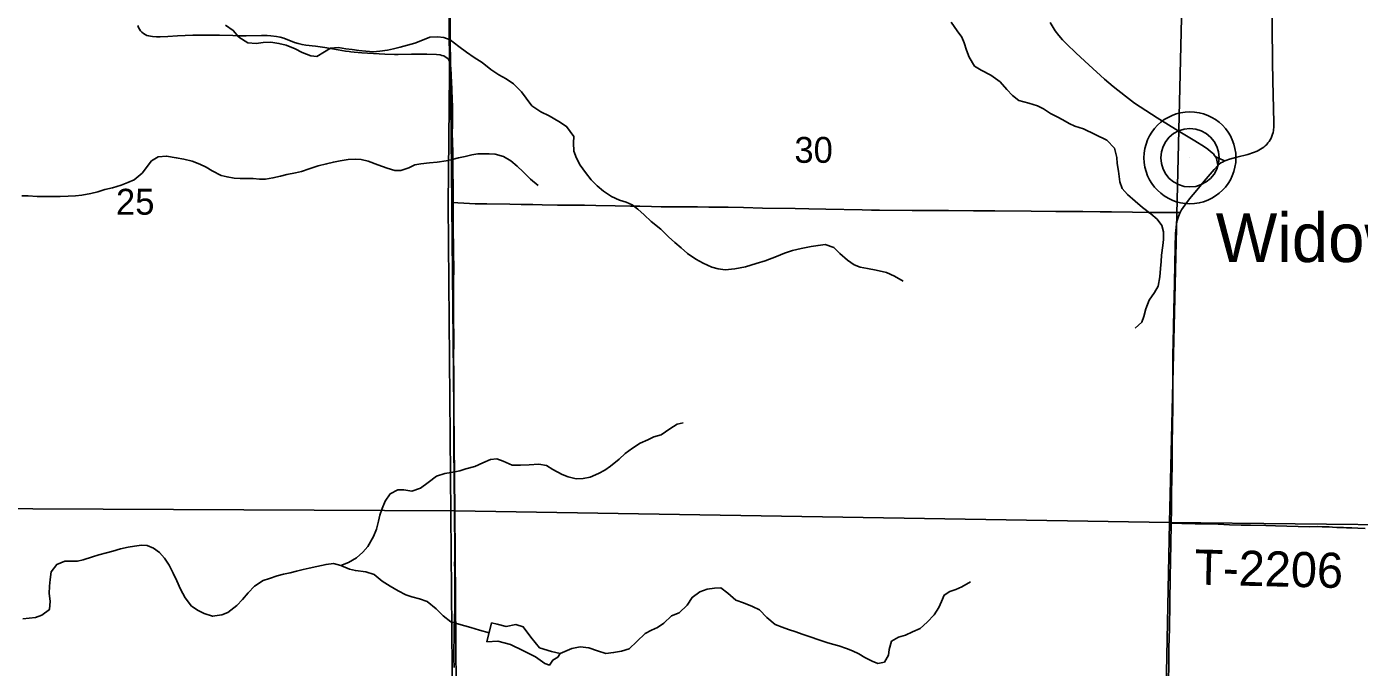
# Model space of a CAD drawing. Extents: x 1874609 to 2204689, y 815661 to 1281160.
# Drawn here: x 2009363 to 2020755, y 997204 to 1002678 of the extents above; entities that cross this region are included whole.
import ezdxf

# ---------------------------------------------------------------- set-up
doc = ezdxf.new("R2010")
doc.units = 0
for name, color, linetype in [('GM_X_County_Road', 7, 'Continuous'), ('GM_X_Minor_Lake', 7, 'Continuous'), ('GM_X_Minor_River', 7, 'Continuous'), ('GM_X_Section', 7, 'Continuous'), ('GM_X_Section_Text', 7, 'Continuous'), ('GM_X_State_Route', 7, 'Continuous'), ('GM_X_Township', 7, 'Continuous'), ('GM_X_Township_Road', 7, 'Continuous'), ('GM_X_Township_Road_Text', 7, 'Continuous'), ('GM_X_Unincorporated', 7, 'Continuous'), ('GM_X_Unincorporated_Location', 7, 'Continuous'), ('GM_X_Unincorporated_Text', 7, 'Continuous')]:
    doc.layers.add(name, color=color, linetype=linetype)

msp = doc.modelspace()

# ---------------------------------------------------------------- linework, layer by layer
at = {"layer": 'GM_X_County_Road'}
for points in [[(2018113, 1002715), (2018137, 1002672), (2018155, 1002644), (2018185, 1002604), (2018217, 1002567), (2018251, 1002531), (2018334, 1002452), (2018443, 1002352), (2018577, 1002230), (2018652, 1002167), (2018755, 1002085), (2018834, 1002026), (2018929, 1001961), (2019026, 1001899), (2019221, 1001779), (2019348, 1001703), (2019432, 1001652), (2019459, 1001633), (2019484, 1001613), (2019508, 1001591), (2019518, 1001579), (2019527, 1001567), (2019528, 1001565)], [(2019528, 1001565), (2019533, 1001552), (2019538, 1001539), (2019541, 1001524), (2019543, 1001510), (2019546, 1001492)], [(2019528, 1001565), (2019550, 1001554), (2019571, 1001545), (2019590, 1001538), (2019606, 1001532)]]:
    msp.add_lwpolyline(points, dxfattribs=at)
at = {"layer": 'GM_X_Minor_Lake'}
for points in [[(2013296, 997421), (2013392, 997429), (2013498, 997399), (2013610, 997346), (2013712, 997294), (2013792, 997238), (2013832, 997224), (2013861, 997266), (2013903, 997290), (2013925, 997322), (2013851, 997340), (2013748, 997372), (2013674, 997461), (2013608, 997549), (2013546, 997569), (2013462, 997553), (2013386, 997573), (2013338, 997583)], [(2013338, 997583), (2013296, 997421)]]:
    msp.add_lwpolyline(points, dxfattribs=at)
at = {"layer": 'GM_X_Minor_River'}
for points in [[(2017266, 1002716), (2017318, 1002642), (2017356, 1002590), (2017378, 1002539), (2017398, 1002479), (2017420, 1002417), (2017466, 1002342), (2017522, 1002306), (2017604, 1002265), (2017684, 1002207), (2017743, 1002142), (2017791, 1002090), (2017845, 1002048), (2017929, 1002025), (2018004, 1002001), (2018054, 1001977), (2018116, 1001936), (2018172, 1001908), (2018222, 1001881), (2018274, 1001851), (2018324, 1001829), (2018398, 1001806)], [(2011064, 1002692), (2011130, 1002647), (2011178, 1002589), (2011254, 1002540), (2011324, 1002536), (2011385, 1002544), (2011451, 1002546), (2011519, 1002535), (2011583, 1002519), (2011659, 1002490), (2011717, 1002458), (2011793, 1002430), (2011843, 1002423), (2011910, 1002463), (2011960, 1002495), (2012028, 1002501), (2012092, 1002490), (2012146, 1002482), (2012204, 1002476), (2012262, 1002468), (2012324, 1002463), (2012381, 1002469), (2012447, 1002477), (2012499, 1002489), (2012557, 1002504), (2012619, 1002520), (2012682, 1002538), (2012760, 1002570), (2012810, 1002588), (2012876, 1002591), (2012930, 1002585), (2012984, 1002567), (2013058, 1002510), (2013122, 1002460), (2013190, 1002415), (2013258, 1002373), (2013332, 1002312), (2013400, 1002266), (2013462, 1002234), (2013524, 1002189), (2013592, 1002123), (2013632, 1002068), (2013682, 1002002), (2013758, 1001951), (2013830, 1001917), (2013912, 1001869), (2013978, 1001826), (2014042, 1001740)], [(2018398, 1001806), (2018596, 1001709), (2018662, 1001639), (2018682, 1001561), (2018686, 1001509), (2018696, 1001443), (2018708, 1001352), (2018728, 1001296), (2018772, 1001244), (2018840, 1001188), (2018902, 1001132), (2018974, 1001078), (2019026, 1001035), (2019068, 1000979), (2019080, 1000925), (2019082, 1000861), (2019074, 1000809), (2019064, 1000727), (2019060, 1000671), (2019055, 1000612), (2019049, 1000542), (2019035, 1000460), (2019005, 1000406), (2018959, 1000342), (2018931, 1000268), (2018913, 1000203), (2018895, 1000153), (2018838, 1000103)], [(2014042, 1001740), (2014038, 1001687), (2014040, 1001615), (2014064, 1001555), (2014094, 1001495), (2014140, 1001431), (2014190, 1001369), (2014240, 1001318), (2014294, 1001274), (2014364, 1001226), (2014432, 1001196), (2014488, 1001178), (2014538, 1001156), (2014588, 1001120), (2014641, 1001072), (2014703, 1001013), (2014783, 1000947), (2014849, 1000883), (2014905, 1000833), (2014959, 1000789), (2015011, 1000741), (2015083, 1000692), (2015147, 1000658), (2015221, 1000624), (2015273, 1000608), (2015335, 1000602), (2015418, 1000610), (2015508, 1000626), (2015598, 1000654), (2015676, 1000678), (2015773, 1000716), (2015841, 1000744), (2015909, 1000766), (2015985, 1000784), (2016069, 1000800), (2016129, 1000810), (2016188, 1000816), (2016264, 1000792), (2016314, 1000740), (2016380, 1000682), (2016438, 1000642), (2016488, 1000624), (2016552, 1000612), (2016626, 1000597), (2016712, 1000577), (2016782, 1000547), (2016855, 1000505)], [(2009323, 1001234), (2009377, 1001232), (2009454, 1001228), (2009524, 1001226), (2009592, 1001228), (2009650, 1001228), (2009718, 1001230), (2009782, 1001232), (2009836, 1001240), (2009911, 1001254), (2009971, 1001268), (2010031, 1001286), (2010097, 1001300), (2010171, 1001324), (2010229, 1001346), (2010282, 1001370), (2010350, 1001426), (2010430, 1001531), (2010488, 1001565), (2010560, 1001573), (2010642, 1001559), (2010707, 1001545), (2010777, 1001530), (2010845, 1001504), (2010897, 1001478), (2010949, 1001448), (2011027, 1001408), (2011077, 1001394), (2011137, 1001384), (2011189, 1001382), (2011248, 1001382), (2011300, 1001380), (2011354, 1001376), (2011406, 1001376), (2011468, 1001386), (2011534, 1001402), (2011588, 1001416), (2011661, 1001430), (2011713, 1001440), (2011777, 1001464), (2011855, 1001490), (2011927, 1001506), (2011985, 1001522), (2012043, 1001532), (2012112, 1001542), (2012172, 1001546), (2012222, 1001544), (2012282, 1001530), (2012364, 1001498), (2012444, 1001468), (2012510, 1001449), (2012562, 1001449), (2012629, 1001472), (2012681, 1001498), (2012733, 1001506), (2012807, 1001514), (2012871, 1001520), (2012949, 1001532), (2013002, 1001544), (2013054, 1001558), (2013112, 1001570), (2013170, 1001584), (2013220, 1001592), (2013316, 1001593), (2013368, 1001589), (2013438, 1001569), (2013503, 1001531), (2013557, 1001487), (2013607, 1001439), (2013671, 1001375), (2013735, 1001321)], [(2012048, 998075), (2012114, 998101), (2012184, 998141), (2012236, 998187), (2012280, 998237), (2012328, 998322), (2012355, 998386), (2012371, 998452), (2012383, 998504), (2012403, 998562), (2012427, 998624), (2012471, 998688), (2012537, 998720), (2012587, 998720), (2012656, 998710), (2012730, 998736), (2012796, 998783), (2012868, 998837), (2012938, 998861), (2012993, 998869), (2013067, 998883), (2013117, 998901), (2013195, 998921), (2013263, 998951), (2013327, 998981), (2013383, 998985), (2013436, 998967), (2013514, 998931), (2013584, 998931), (2013658, 998935), (2013742, 998940), (2013806, 998930), (2013862, 998894), (2013941, 998852), (2013991, 998832), (2014061, 998816), (2014121, 998818), (2014179, 998830), (2014251, 998860), (2014305, 998888), (2014355, 998924), (2014428, 998984), (2014480, 999030), (2014542, 999078), (2014608, 999119), (2014672, 999149), (2014725, 999173), (2014787, 999191), (2014861, 999243), (2014923, 999281), (2014975, 999293)], [(2009331, 997619), (2009385, 997623), (2009438, 997631), (2009494, 997649), (2009558, 997697), (2009564, 997769), (2009556, 997836), (2009558, 997898), (2009564, 997956), (2009574, 998020), (2009620, 998082), (2009689, 998110), (2009739, 998112), (2009797, 998110), (2009847, 998122), (2009927, 998148), (2009981, 998166), (2010047, 998182), (2010100, 998198), (2010166, 998216), (2010232, 998232), (2010284, 998240), (2010344, 998248), (2010394, 998244), (2010448, 998222), (2010498, 998186), (2010542, 998136), (2010582, 998078), (2010616, 998010), (2010646, 997943), (2010678, 997873), (2010718, 997799), (2010772, 997727), (2010829, 997689), (2010881, 997663), (2010953, 997640), (2011033, 997654), (2011083, 997672), (2011161, 997733), (2011207, 997783), (2011256, 997841), (2011310, 997899), (2011384, 997945), (2011438, 997963), (2011504, 997985), (2011558, 997999), (2011617, 998013), (2011669, 998027), (2011727, 998041), (2011777, 998051), (2011843, 998065), (2011923, 998083), (2011985, 998091), (2012048, 998075)], [(2012048, 998075), (2012122, 998043), (2012174, 998031), (2012262, 998021), (2012334, 997997), (2012402, 997941), (2012470, 997898), (2012538, 997858), (2012605, 997824), (2012655, 997806), (2012721, 997790), (2012787, 997766), (2012865, 997704), (2012925, 997644), (2012989, 997593), (2013059, 997573), (2013159, 997545), (2013234, 997523), (2013316, 997500)], [(2013925, 997322), (2014023, 997366), (2014095, 997378), (2014169, 997370), (2014243, 997346), (2014314, 997322), (2014380, 997330), (2014448, 997342), (2014514, 997362), (2014580, 997424), (2014649, 997492), (2014705, 997522), (2014757, 997544), (2014809, 997581), (2014875, 997643), (2014941, 997671), (2015010, 997735), (2015052, 997801), (2015118, 997849), (2015180, 997871), (2015244, 997881), (2015298, 997883), (2015358, 997837), (2015426, 997779), (2015491, 997755), (2015569, 997723), (2015627, 997696), (2015691, 997630), (2015761, 997570), (2015821, 997546), (2015875, 997528), (2015937, 997508), (2015991, 997488), (2016061, 997464), (2016136, 997438), (2016202, 997417), (2016252, 997401), (2016306, 997387), (2016370, 997365), (2016422, 997345), (2016476, 997319), (2016528, 997287), (2016590, 997257), (2016640, 997237), (2016695, 997247), (2016729, 997307), (2016737, 997357), (2016755, 997427), (2016817, 997461), (2016875, 997479), (2016935, 997507), (2017000, 997537), (2017060, 997590), (2017120, 997652), (2017162, 997714), (2017184, 997766), (2017206, 997822), (2017256, 997852), (2017307, 997870), (2017357, 997892), (2017431, 997936)]]:
    msp.add_lwpolyline(points, dxfattribs=at)
at = {"layer": 'GM_X_Section'}
for points in [[(2007611, 1003961), (2008513, 1003979), (2012981, 1003882), (2012972, 1003772), (2013022, 998540), (2007609, 998568)], [(2012972, 1003772), (2019259, 1003713), (2019131, 998443), (2013022, 998540)], [(2024581, 1003656), (2024502, 998386), (2019131, 998443), (2019259, 1003713)], [(2007609, 998568), (2013022, 998540), (2013063, 993254), (2007884, 993256)], [(2013022, 998540), (2019131, 998443), (2019028, 993166), (2013063, 993254)], [(2019131, 998443), (2024502, 998386), (2024403, 993136), (2024347, 993135), (2019028, 993166)]]:
    msp.add_lwpolyline(points, close=True, dxfattribs=at)
at = {"layer": 'GM_X_State_Route'}
msp.add_lwpolyline([(2019124, 997093), (2019126, 997224), (2019128, 997371), (2019131, 997535), (2019139, 997978), (2019141, 998109), (2019146, 998421), (2019146, 998435), (2019149, 998552), (2019150, 998683), (2019153, 998830), (2019154, 998913), (2019156, 999093), (2019159, 999290), (2019160, 999404), (2019161, 999552), (2019162, 999732), (2019162, 999880), (2019163, 999978), (2019170, 1000256), (2019174, 1000486), (2019178, 1000650), (2019181, 1000797), (2019185, 1000912), (2019188, 1000961), (2019192, 1000993), (2019197, 1001023), (2019208, 1001055), (2019221, 1001085), (2019224, 1001091), (2019236, 1001113), (2019264, 1001154), (2019303, 1001206), (2019365, 1001282), (2019429, 1001358), (2019513, 1001458), (2019546, 1001492), (2019552, 1001498), (2019558, 1001504), (2019571, 1001514), (2019585, 1001522), (2019599, 1001530), (2019606, 1001532), (2019614, 1001535), (2019645, 1001546), (2019708, 1001562), (2019803, 1001587), (2019851, 1001602), (2019881, 1001615), (2019911, 1001631), (2019925, 1001640), (2019938, 1001650), (2019951, 1001661), (2019963, 1001672), (2019974, 1001685), (2019984, 1001698), (2019993, 1001712), (2020001, 1001727), (2020008, 1001743), (2020013, 1001759), (2020018, 1001775), (2020021, 1001791), (2020024, 1001824), (2020025, 1001857), (2020017, 1002218), (2020013, 1002374), (2020013, 1002481), (2020011, 1002579), (2020009, 1002760)], dxfattribs=at)
at = {"layer": 'GM_X_Township'}
for points in [[(2012831, 1025242), (2012842, 1023548), (2012864, 1022217), (2012856, 1019844), (2012859, 1019536), (2012902, 1015157), (2012905, 1014539), (2012906, 1014236), (2012920, 1010262), (2012927, 1008778), (2012962, 1005114), (2012978, 1002278), (2012967, 1001159), (2013012, 995874)], [(2013012, 995874), (2012967, 1001159), (2012978, 1002278), (2012962, 1005114), (2012927, 1008778), (2012920, 1010262), (2012906, 1014236), (2012905, 1014539), (2012902, 1015157), (2012859, 1019536), (2012856, 1019844), (2012864, 1022217), (2012842, 1023548), (2012831, 1025242), (2013359, 1025237), (2014559, 1025225), (2018880, 1025183), (2019555, 1025177), (2023338, 1025140), (2030478, 1025070), (2037504, 1025002)]]:
    msp.add_lwpolyline(points, dxfattribs=at)
at = {"layer": 'GM_X_Township_Road'}
for points in [[(2010315, 1002688), (2010320, 1002672), (2010328, 1002658), (2010337, 1002643), (2010349, 1002631), (2010361, 1002621), (2010375, 1002611), (2010390, 1002604), (2010407, 1002599), (2010423, 1002596), (2010440, 1002593), (2010473, 1002592), (2010505, 1002592), (2010571, 1002595), (2010652, 1002600), (2010783, 1002605), (2010930, 1002606), (2011012, 1002605), (2011126, 1002602), (2011175, 1002601), (2011241, 1002600), (2011372, 1002603), (2011420, 1002602), (2011451, 1002600), (2011499, 1002594), (2011530, 1002588), (2011562, 1002579), (2011654, 1002544), (2011685, 1002535), (2011717, 1002526), (2011750, 1002521), (2011831, 1002511), (2011912, 1002501), (2012025, 1002481), (2012088, 1002470), (2012119, 1002465), (2012134, 1002464), (2012164, 1002461), (2012229, 1002456), (2012425, 1002443), (2012507, 1002441), (2012540, 1002441)], [(2012540, 1002441), (2012654, 1002443), (2012785, 1002444), (2012866, 1002440), (2012898, 1002437), (2012913, 1002433), (2012928, 1002428), (2012942, 1002422), (2012955, 1002412), (2012965, 1002403), (2012972, 1002392), (2012977, 1002381)], [(2012977, 1002381), (2012980, 1002374), (2012984, 1002358), (2012987, 1002343), (2012989, 1002327), (2012993, 1002262), (2012998, 1002148), (2013002, 1002050), (2013004, 1002001), (2013004, 1001935), (2013003, 1001853), (2013002, 1001755), (2013003, 1001706), (2013005, 1001592), (2013005, 1001526), (2013007, 1001444), (2013010, 1001314), (2013010, 1001248), (2013009, 1001177)], [(2013022, 998304), (2013022, 998327), (2013020, 998392), (2013020, 998473), (2013020, 998572), (2013021, 998637), (2013020, 998670), (2013019, 998701), (2013019, 998727), (2013018, 998750), (2013018, 998769), (2013018, 998792), (2013018, 998815), (2013017, 998837), (2013017, 998858), (2013017, 998872), (2013017, 998894), (2013015, 999007), (2013015, 999187), (2013015, 999252), (2013015, 999269), (2013015, 999318), (2013015, 999399), (2013015, 999464), (2013016, 999529), (2013015, 999594), (2013014, 999676), (2013014, 999757), (2013013, 999806), (2013013, 999888), (2013014, 999953), (2013015, 1000018), (2013014, 1000051), (2013013, 1000148), (2013012, 1000246), (2013013, 1000327), (2013013, 1000409), (2013013, 1000475), (2013015, 1000639), (2013013, 1000721), (2013012, 1000770), (2013011, 1000819), (2013010, 1000916), (2013009, 1000982), (2013008, 1001031), (2013008, 1001096), (2013009, 1001177)], [(2013009, 1001177), (2013050, 1001173), (2013099, 1001169), (2013197, 1001165), (2013296, 1001164), (2013493, 1001161), (2013591, 1001160), (2013689, 1001158), (2013771, 1001156), (2013902, 1001154), (2014000, 1001153), (2014049, 1001153), (2014131, 1001152), (2014229, 1001150), (2014393, 1001147), (2014524, 1001145), (2014606, 1001144), (2014705, 1001141), (2014786, 1001139), (2014884, 1001138), (2014999, 1001138), (2015097, 1001138), (2015195, 1001137), (2015359, 1001135), (2015490, 1001132), (2015654, 1001129), (2015933, 1001125), (2016048, 1001123), (2016195, 1001120), (2016506, 1001112), (2016586, 1001111)], [(2016586, 1001111), (2016654, 1001110), (2016933, 1001109), (2017080, 1001109), (2017244, 1001107), (2017457, 1001105), (2017556, 1001104), (2017638, 1001104), (2017949, 1001102), (2018162, 1001100), (2018276, 1001099), (2018391, 1001098), (2018539, 1001096), (2018637, 1001096), (2018817, 1001093), (2018949, 1001090), (2019080, 1001091), (2019162, 1001091), (2019224, 1001091)], [(2019146, 998435), (2019188, 998435), (2019237, 998434), (2019352, 998431), (2019483, 998429), (2019548, 998427), (2019646, 998423), (2019744, 998420), (2019825, 998418), (2019956, 998416), (2020038, 998413), (2020233, 998408), (2020331, 998406), (2020396, 998407), (2020436, 998405), (2020459, 998404), (2020497, 998404), (2020526, 998401), (2020564, 998400), (2020587, 998399), (2020620, 998398), (2020646, 998396), (2020690, 998395), (2020741, 998393), (2020805, 998390)], [(2013018, 997202), (2013016, 997283), (2013015, 997365), (2013018, 997446), (2013019, 997496), (2013019, 997552), (2013020, 997598), (2013021, 997638), (2013022, 997690), (2013022, 997733), (2013023, 997806), (2013023, 997855), (2013023, 997888), (2013023, 997922), (2013023, 997960), (2013023, 997993), (2013022, 998051), (2013021, 998083), (2013022, 998131), (2013022, 998180), (2013022, 998238), (2013022, 998281), (2013022, 998304)]]:
    msp.add_lwpolyline(points, dxfattribs=at)
at = {"layer": 'GM_X_Unincorporated'}
for radius in [393, 249]:
    msp.add_circle((2019307, 1001558), radius, dxfattribs=at)
at = {"layer": 'GM_X_Unincorporated_Location'}
msp.add_line((2019307, 1001558), (2019307, 1001558), dxfattribs=at)

# ---------------------------------------------------------------- texts
at = {"layer": 'GM_X_Section_Text'}
for s, p in [('30', (2015926, 1001515)), ('25', (2010127, 1001072))]:
    msp.add_text(s, height=221, rotation=0, dxfattribs=at).set_placement(p)
at = {"layer": 'GM_X_Township_Road_Text'}
msp.add_text('T-2206', height=300, rotation=358.6147, dxfattribs=at).set_placement((2019342, 997912))
at = {"layer": 'GM_X_Unincorporated_Text'}
msp.add_text('Widowville', height=417, rotation=0, dxfattribs=at).set_placement((2019528, 1000667))

doc.saveas('drawing.dxf')
